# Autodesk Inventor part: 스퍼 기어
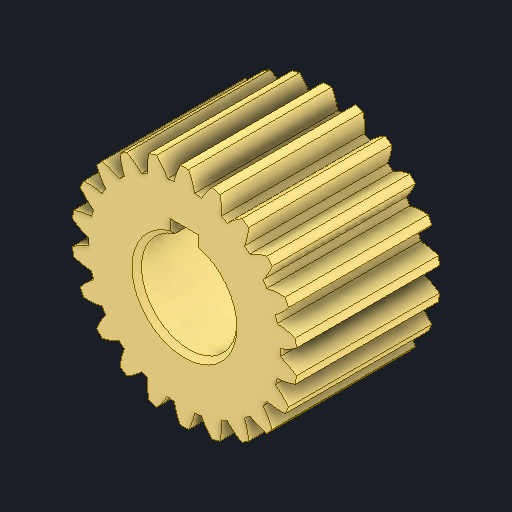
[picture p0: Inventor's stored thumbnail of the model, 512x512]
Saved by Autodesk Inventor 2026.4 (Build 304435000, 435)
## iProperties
Created: 2026-09
Part Number: 스퍼 기어
Material: 강철, 합금
Document SubType Name: Modeling
Designer: user
Density: 7.73 g/cm^3
Appearance: 기본값
Author: jhkim
Sending System: Autodesk Inventor 2027
Preprocessor: ST-DEVELOPER v20.1
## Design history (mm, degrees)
feature "Solid1"
node "솔리드1"
